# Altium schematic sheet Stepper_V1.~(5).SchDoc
size A4; SheetNumber: 4; SheetTotal: 7
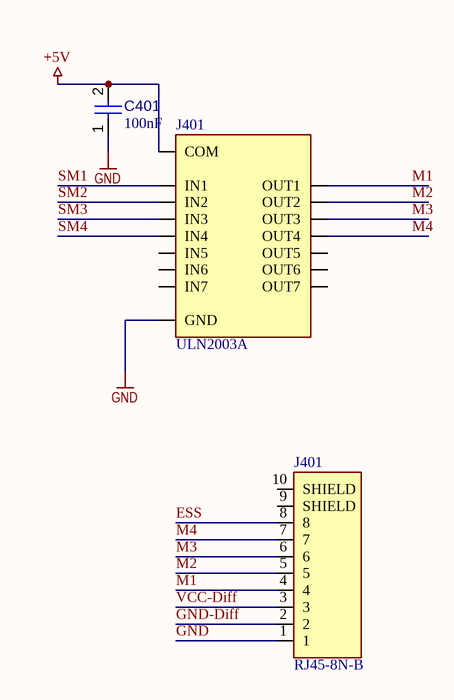
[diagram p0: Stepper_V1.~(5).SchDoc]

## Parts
(Parts that share a designator on the sheet are numbered #1, #2 ... from top to bottom, then left to right.)
C401  value 100nF  [CAPC1608X90X40NL10T20]  (hidden comment: Capacitor 100 nF +/-10% 50 V 0603)
J401#1  ULN2003A  [TSSOP-16-TI]
J401#2  RJ45-8N-B  [TE_RJ45-8N-B]

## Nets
+5V: C401.2 J401#1.9(COM)
GND: C401.1 J401#1.8(GND) J401#2.1
ESS: J401#2.8
GND-Diff: J401#2.2
M1: J401#1.16(OUT1) J401#2.4
M2: J401#1.15(OUT2) J401#2.5
M3: J401#1.14(OUT3) J401#2.6
M4: J401#1.13(OUT4) J401#2.7
SM1: J401#1.1(IN1)
SM2: J401#1.2(IN2)
SM3: J401#1.3(IN3)
SM4: J401#1.4(IN4)
VCC-Diff: J401#2.3

Not connected (* = marked no-connect by the designer): J401#1 5(IN5) 6(IN6) 7(IN7) 10(OUT7) 11(OUT6) 12(OUT5); J401#2 9(SHIELD) 10(SHIELD)

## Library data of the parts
C401 = CMP-001-00017-6: Chip Capacitor, 100 nF, +/- 10%, 50 V, 0603 (1608 Metric); Voltage Rating: 50V; Capacitor Type: Ceramic
J401#1 = ULN2003A: DARLINGTON ARRAY 7NPN, 2003, DIP16; Transistor Polarity:NPN; Collector Emitter Voltage V(br)ceo:50V; DC Collector Current:500mA; DC Current Gain hFE:1000; Operating Temperature Range:-20Â°C to +85Â°C; Transistor Case Style:DIP; No. of Pins:16; SVHC:No SVH; MF: STMicroelectronics
J401#2 = RJ45-8N-B: RJ Jack / Signal Line EMI/RFI Filters 6 TERM LOW PROFILE BLOCK INDUCTOR 8 PIN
